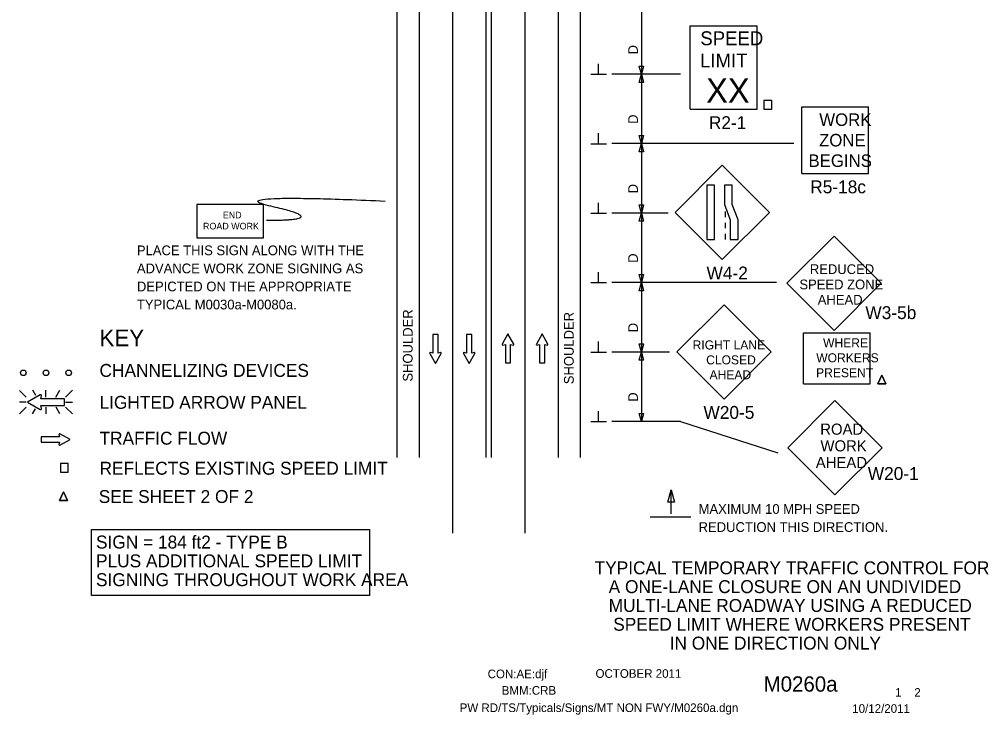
# Model space of a CAD drawing. Extents: x 16747 to 18480, y 5932 to 6921.
# Drawn here: x 16754 to 17451, y 5932 to 6432 of the extents above; entities that cross this region are included whole.
import ezdxf

# ---------------------------------------------------------------- set-up
doc = ezdxf.new("R2010")
doc.units = 0
for name, color, linetype in [('ALI_LEGAL_EX', 7, 'Continuous'), ('BORDER', 7, 'Continuous'), ('BORDER_SIGNAL_WO', 7, 'Continuous'), ('MT_SCRATCH_LEVEL_E', 7, 'Continuous'), ('PAVT_EDGE_EX', 7, 'Continuous'), ('TRAFFIC_SIGNS_PR', 7, 'Continuous'), ('TYPICAL_TEXT_DIMEN_EX', 7, 'Continuous'), ('TYPICAL_TEXT_DIMEN_PR', 7, 'Continuous')]:
    doc.layers.add(name, color=color, linetype=linetype)

msp = doc.modelspace()

# ---------------------------------------------------------------- linework, layer by layer
at = {"layer": 'ALI_LEGAL_EX'}
for p, q in [((17065.33, 6891.74), (17065.33, 6062.55)), ((17117.33, 6891.74), (17117.33, 6062.55))]:
    msp.add_line(p, q, dxfattribs=at)
for points in [[(17065.33, 6409.08), (17065.33, 6384.08)], [(17117.33, 6409.08), (17117.33, 6384.08)], [(17065.33, 6309.08), (17065.33, 6284.08)], [(17117.33, 6309.08), (17117.33, 6284.08)], [(17065.33, 6209.08), (17065.33, 6184.08)], [(17117.33, 6209.08), (17117.33, 6184.08)]]:
    msp.add_lwpolyline(points, dxfattribs=at)
at = {"layer": 'MT_SCRATCH_LEVEL_E'}
for p, q in [((17055, 6205.36), (17051.26, 6205.36)), ((17051.26, 6205.36), (17051.26, 6192.1)), ((17055, 6205.36), (17051.26, 6205.36)), ((17051.26, 6205.36), (17051.26, 6192.1)), ((17055, 6192.1), (17055, 6205.36)), ((17055, 6192.1), (17055, 6205.36)), ((17079.25, 6205.36), (17075.51, 6205.36)), ((17075.51, 6205.36), (17075.51, 6192.1)), ((17079.25, 6205.36), (17075.51, 6205.36)), ((17075.51, 6205.36), (17075.51, 6192.1)), ((17079.25, 6192.1), (17079.25, 6205.36)), ((17079.25, 6192.1), (17079.25, 6205.36)), ((17105.3, 6205.82), (17101.19, 6198.58)), ((17105.3, 6205.82), (17101.19, 6198.58)), ((17109.44, 6198.58), (17105.3, 6205.82)), ((17109.44, 6198.58), (17105.3, 6205.82)), ((17129.85, 6205.82), (17125.74, 6198.58)), ((17129.85, 6205.82), (17125.74, 6198.58)), ((17134, 6198.58), (17129.85, 6205.82)), ((17134, 6198.58), (17129.85, 6205.82)), ((17101.67, 6197.89), (17103.44, 6198.21)), ((17101.67, 6197.89), (17103.44, 6198.21)), ((17103.44, 6198.21), (17103.44, 6184.95)), ((17103.44, 6198.21), (17103.44, 6184.95)), ((17107.19, 6184.95), (17107.19, 6198.21)), ((17107.19, 6198.21), (17108.96, 6197.89)), ((17107.19, 6184.95), (17107.19, 6198.21)), ((17107.19, 6198.21), (17108.96, 6197.89)), ((17126.22, 6197.89), (17128, 6198.21)), ((17126.22, 6197.89), (17128, 6198.21)), ((17128, 6198.21), (17128, 6184.95)), ((17128, 6198.21), (17128, 6184.95)), ((17131.74, 6184.95), (17131.74, 6198.21)), ((17131.74, 6198.21), (17133.52, 6197.89)), ((17131.74, 6184.95), (17131.74, 6198.21)), ((17131.74, 6198.21), (17133.52, 6197.89)), ((17049, 6191.73), (17053.15, 6184.49)), ((17049, 6191.73), (17053.15, 6184.49)), ((17051.26, 6192.1), (17049.48, 6192.42)), ((17051.26, 6192.1), (17049.48, 6192.42)), ((17053.15, 6184.49), (17057.26, 6191.73)), ((17053.15, 6184.49), (17057.26, 6191.73)), ((17056.78, 6192.42), (17055, 6192.1)), ((17056.78, 6192.42), (17055, 6192.1)), ((17073.26, 6191.73), (17077.4, 6184.49)), ((17073.26, 6191.73), (17077.4, 6184.49)), ((17075.51, 6192.1), (17073.73, 6192.42)), ((17075.51, 6192.1), (17073.73, 6192.42)), ((17077.4, 6184.49), (17081.51, 6191.73)), ((17077.4, 6184.49), (17081.51, 6191.73)), ((17081.03, 6192.42), (17079.25, 6192.1)), ((17081.03, 6192.42), (17079.25, 6192.1)), ((17103.44, 6184.95), (17107.19, 6184.95)), ((17103.44, 6184.95), (17107.19, 6184.95)), ((17128, 6184.95), (17131.74, 6184.95)), ((17128, 6184.95), (17131.74, 6184.95)), ((16782.67, 6131.69), (16769.41, 6131.69)), ((16769.41, 6131.69), (16769.41, 6127.95)), ((16782.67, 6131.69), (16769.41, 6131.69)), ((16769.41, 6131.69), (16769.41, 6127.95)), ((16782.35, 6133.47), (16782.67, 6131.69)), ((16782.35, 6133.47), (16782.67, 6131.69)), ((16790.28, 6129.84), (16783.03, 6133.95)), ((16790.28, 6129.84), (16783.03, 6133.95)), ((16783.03, 6125.69), (16790.28, 6129.84)), ((16783.03, 6125.69), (16790.28, 6129.84)), ((16769.41, 6127.95), (16782.67, 6127.95)), ((16769.41, 6127.95), (16782.67, 6127.95)), ((16782.67, 6127.95), (16782.35, 6126.17)), ((16782.67, 6127.95), (16782.35, 6126.17))]:
    msp.add_line(p, q, dxfattribs=at)
for centre, start, end in [((17101.59, 6198.35), 150.42484, 279.96381), ((17101.59, 6198.35), 150.42484, 279.96381), ((17109.03, 6198.35), 260.03619, 29.77312), ((17109.03, 6198.35), 260.03619, 29.77312), ((17126.15, 6198.35), 150.42484, 279.96381), ((17126.15, 6198.35), 150.42484, 279.96381), ((17133.59, 6198.35), 260.03619, 29.77312), ((17133.59, 6198.35), 260.03619, 29.77312), ((17049.41, 6191.96), 80.03619, 209.77312), ((17049.41, 6191.96), 80.03619, 209.77312), ((17056.85, 6191.96), 330.42484, 99.96381), ((17056.85, 6191.96), 330.42484, 99.96381), ((17073.66, 6191.96), 80.03619, 209.77312), ((17073.66, 6191.96), 80.03619, 209.77312), ((17081.11, 6191.96), 330.42484, 99.96381), ((17081.11, 6191.96), 330.42484, 99.96381), ((16782.81, 6133.54), 60.42484, 189.96381), ((16782.81, 6133.54), 60.42484, 189.96381), ((16782.81, 6126.1), 170.03619, 299.77312), ((16782.81, 6126.1), 170.03619, 299.77312)]:
    msp.add_arc(centre, 0.463, start, end, dxfattribs=at)
at = {"layer": 'PAVT_EDGE_EX'}
for p, q in [((17025.33, 6921.02), (17025.33, 6117.01)), ((17041.33, 6921.02), (17041.33, 6117.01)), ((17089.33, 6921.02), (17089.33, 6117.01)), ((17093.33, 6921.02), (17093.33, 6117.01)), ((17141.33, 6921.02), (17141.33, 6117.01)), ((17157.33, 6921.02), (17157.33, 6117.01))]:
    msp.add_line(p, q, dxfattribs=at)
at = {"layer": 'TRAFFIC_SIGNS_PR'}
for p, q in [((17236.44, 6427.59), (17284.44, 6427.59)), ((17236.44, 6367.59), (17236.44, 6427.59)), ((17284.44, 6367.59), (17284.44, 6427.59)), ((17236.44, 6367.59), (17284.44, 6367.59)), ((17316.72, 6321.36), (17316.72, 6369.36)), ((17316.72, 6369.36), (17364.72, 6369.36)), ((17364.72, 6321.36), (17364.72, 6369.36)), ((17259.43, 6327.25), (17225.49, 6293.31)), ((17293.37, 6293.31), (17259.43, 6327.25)), ((17316.72, 6321.36), (17364.72, 6321.36)), ((17225.49, 6293.31), (17259.43, 6259.37)), ((17259.43, 6259.37), (17293.37, 6293.31)), ((17261.48, 6293.92), (17261.48, 6289.92)), ((17261.48, 6285.92), (17261.48, 6281.92)), ((17261.48, 6277.92), (17261.48, 6273.92)), ((17339.86, 6276.29), (17305.92, 6242.35)), ((17373.8, 6242.35), (17339.86, 6276.29)), ((17305.92, 6242.35), (17339.86, 6208.41)), ((17339.86, 6208.41), (17373.8, 6242.35)), ((17260.71, 6226.89), (17226.77, 6192.95)), ((17294.65, 6192.95), (17260.71, 6226.89)), ((17317.81, 6206.59), (17365.81, 6206.59)), ((17317.81, 6169.94), (17317.81, 6206.59)), ((17365.81, 6169.94), (17365.81, 6206.59)), ((17226.77, 6192.95), (17260.71, 6159.01)), ((17260.71, 6159.01), (17294.65, 6192.95)), ((16753.86, 6165.26), (16758.79, 6160.33)), ((16765.62, 6161.44), (16763.42, 6165.27)), ((16772.94, 6160.33), (16772.94, 6165.27)), ((16780.18, 6160.33), (16783.03, 6165.27)), ((16787.09, 6160.33), (16792.03, 6165.27)), ((17317.81, 6169.94), (17365.81, 6169.94)), ((16758.79, 6156.78), (16753.86, 6156.78)), ((16787.09, 6156.78), (16792.03, 6156.78)), ((17340.51, 6157.84), (17306.57, 6123.89)), ((17374.45, 6123.89), (17340.51, 6157.84)), ((16753.86, 6148.29), (16758.79, 6153.22)), ((16763.37, 6148.28), (16765.48, 6151.95)), ((16772.94, 6153.22), (16772.94, 6148.28)), ((16783.07, 6148.28), (16780.22, 6153.22)), ((16787.09, 6153.22), (16792.03, 6148.28)), ((17306.57, 6123.89), (17340.51, 6089.95)), ((17340.51, 6089.95), (17374.45, 6123.89))]:
    msp.add_line(p, q, dxfattribs=at)
for points in [[(17289.46, 6367.59), (17295.05, 6367.59), (17295.05, 6373.76), (17289.46, 6373.76)], [(17248.31, 6312.98), (17248.31, 6273.92), (17253.93, 6273.92), (17253.93, 6312.98)], [(17260.98, 6312.98), (17260.98, 6299), (17265.16, 6287.9), (17265.16, 6273.92), (17270.78, 6273.92), (17270.78, 6287.9), (17266.6, 6299), (17266.6, 6312.98)], [(16881.45, 6275.13), (16929.45, 6275.13), (16929.45, 6299.13), (16881.45, 6299.13)], [(16783.33, 6106.37), (16788.92, 6106.37), (16788.92, 6112.54), (16783.33, 6112.54)]]:
    msp.add_lwpolyline(points, close=True, dxfattribs=at)
for points in [[(17374.25, 6176.11), (17371.45, 6169.94)], [(17371.45, 6169.94), (17374.25, 6176.11)], [(17377.04, 6169.94), (17374.25, 6176.11)], [(17374.25, 6176.11), (17377.04, 6169.94)], [(17371.45, 6169.94), (17377.04, 6169.94)], [(17377.04, 6169.94), (17371.45, 6169.94)], [(16768.87, 6162.05), (16759.58, 6156.78), (16768.87, 6151.45)], [(16769.74, 6152.08), (16769.34, 6154.35), (16786.36, 6154.35), (16786.36, 6159.15), (16769.34, 6159.15), (16769.75, 6161.43)], [(16785.58, 6092.18), (16782.78, 6086.01)], [(16782.78, 6086.01), (16785.58, 6092.18)], [(16788.37, 6086.01), (16785.58, 6092.18)], [(16785.58, 6092.18), (16788.37, 6086.01)], [(16782.78, 6086.01), (16788.37, 6086.01)], [(16788.37, 6086.01), (16782.78, 6086.01)]]:
    msp.add_lwpolyline(points, dxfattribs=at)
for centre in [(16756.65, 6177.89), (16772.95, 6177.89), (16789.25, 6177.89)]:
    msp.add_circle(centre, 2, dxfattribs=at)
for centre, radius, start, end in [((16769.16, 6161.53), 0.598, 350.73078, 118.89165), ((16769.16, 6151.98), 0.597, 241.48329, 9.95933)]:
    msp.add_arc(centre, radius, start, end, dxfattribs=at)
msp.add_open_spline([(16931.67, 6287.67), (16978.9, 6287.67), (16893.88, 6307.02), (17016.98, 6301.53)], degree=2, dxfattribs=at)
at = {"layer": 'TYPICAL_TEXT_DIMEN_EX'}
msp.add_lwpolyline([(16805.73, 6065.18), (17005.7, 6065.18), (17005.7, 6017.51), (16805.73, 6017.51)], close=True, dxfattribs=at)
at = {"layer": 'TYPICAL_TEXT_DIMEN_PR'}
for p, q in [((17201.33, 6442.82), (17201.33, 6392.82)), ((17170.45, 6392.52), (17170.45, 6400.3)), ((17201.33, 6392.82), (17199.76, 6398.68)), ((17199.76, 6398.68), (17201.33, 6398.68)), ((17201.33, 6398.68), (17202.9, 6398.68)), ((17202.9, 6398.68), (17201.33, 6392.82)), ((17201.33, 6397.69), (17201.33, 6393.92)), ((17176.08, 6392.52), (17164.83, 6392.52)), ((17229.37, 6392.82), (17180.12, 6392.82)), ((17199.76, 6386.95), (17201.33, 6392.82)), ((17201.33, 6386.95), (17199.76, 6386.95)), ((17201.33, 6392.82), (17201.33, 6342.82)), ((17201.33, 6392.82), (17202.9, 6386.95)), ((17202.9, 6386.95), (17201.33, 6386.95)), ((17170.45, 6342.52), (17170.45, 6350.3)), ((17201.33, 6342.82), (17199.76, 6348.68)), ((17199.76, 6348.68), (17201.33, 6348.68)), ((17201.33, 6348.68), (17202.9, 6348.68)), ((17202.9, 6348.68), (17201.33, 6342.82)), ((17201.33, 6347.69), (17201.33, 6343.92)), ((17176.08, 6342.52), (17164.83, 6342.52)), ((17311.02, 6342.82), (17180.12, 6342.82)), ((17199.76, 6336.95), (17201.33, 6342.82)), ((17201.33, 6342.82), (17201.33, 6292.82)), ((17201.33, 6342.82), (17202.9, 6336.95)), ((17201.33, 6336.95), (17199.76, 6336.95)), ((17202.9, 6336.95), (17201.33, 6336.95)), ((17170.45, 6292.52), (17170.45, 6300.3)), ((17201.33, 6292.82), (17199.76, 6298.68)), ((17199.76, 6298.68), (17201.33, 6298.68)), ((17201.33, 6298.68), (17202.9, 6298.68)), ((17202.9, 6298.68), (17201.33, 6292.82)), ((17201.33, 6297.69), (17201.33, 6293.92)), ((17176.08, 6292.52), (17164.83, 6292.52)), ((17220.6, 6292.82), (17180.12, 6292.82)), ((17199.76, 6286.95), (17201.33, 6292.82)), ((17201.33, 6292.82), (17201.33, 6242.82)), ((17201.33, 6292.82), (17202.9, 6286.95)), ((17201.33, 6286.95), (17199.76, 6286.95)), ((17202.9, 6286.95), (17201.33, 6286.95)), ((17170.45, 6242.52), (17170.45, 6250.3)), ((17201.33, 6242.82), (17199.76, 6248.68)), ((17199.76, 6248.68), (17201.33, 6248.68)), ((17201.33, 6248.68), (17202.9, 6248.68)), ((17202.9, 6248.68), (17201.33, 6242.82)), ((17201.33, 6247.69), (17201.33, 6243.92)), ((17176.08, 6242.52), (17164.83, 6242.52)), ((17298.38, 6242.82), (17180.12, 6242.82)), ((17199.76, 6236.95), (17201.33, 6242.82)), ((17201.33, 6242.82), (17201.33, 6192.82)), ((17201.33, 6242.82), (17202.9, 6236.95)), ((17201.33, 6236.95), (17199.76, 6236.95)), ((17202.9, 6236.95), (17201.33, 6236.95)), ((17170.45, 6192.52), (17170.45, 6200.3)), ((17201.33, 6192.82), (17199.76, 6198.68)), ((17199.76, 6198.68), (17201.33, 6198.68)), ((17201.33, 6198.68), (17202.9, 6198.68)), ((17202.9, 6198.68), (17201.33, 6192.82)), ((17176.08, 6192.52), (17164.83, 6192.52)), ((17221.41, 6192.82), (17180.12, 6192.82)), ((17199.76, 6186.95), (17201.33, 6192.82)), ((17201.33, 6197.69), (17201.33, 6193.92)), ((17201.33, 6192.82), (17201.33, 6142.82)), ((17201.33, 6192.82), (17202.9, 6186.95)), ((17201.33, 6186.95), (17199.76, 6186.95)), ((17202.9, 6186.95), (17201.33, 6186.95)), ((17170.45, 6142.52), (17170.45, 6150.3)), ((17176.08, 6142.52), (17164.83, 6142.52)), ((17229.37, 6142.82), (17180.12, 6142.82)), ((17201.33, 6142.82), (17199.76, 6148.68)), ((17199.76, 6148.68), (17201.33, 6148.68)), ((17201.33, 6148.68), (17202.9, 6148.68)), ((17202.9, 6148.68), (17201.33, 6142.82)), ((17201.33, 6147.69), (17201.33, 6143.92)), ((17229.37, 6142.82), (17299.53, 6120.34)), ((17220.38, 6084.76), (17222.74, 6093.55)), ((17222.74, 6076.43), (17222.74, 6093.55)), ((17222.74, 6093.55), (17225.09, 6084.76)), ((17222.74, 6084.76), (17220.38, 6084.76)), ((17225.09, 6084.76), (17222.74, 6084.76)), ((17236.91, 6073.93), (17207.47, 6073.93))]:
    msp.add_line(p, q, dxfattribs=at)

# ---------------------------------------------------------------- texts
at = {"layer": 'BORDER'}
for s, p in [('TYPICAL TEMPORARY TRAFFIC CONTROL FOR', (17167.63, 6032.86)), ('A ONE-LANE CLOSURE ON AN UNDIVIDED', (17177.73, 6019.31)), ('MULTI-LANE ROADWAY USING A REDUCED', (17177.73, 6005.76)), ('SPEED LIMIT WHERE WORKERS PRESENT', (17181.01, 5992.21)), ('IN ONE DIRECTION ONLY', (17221.59, 5978.66))]:
    msp.add_text(s, height=9.3, dxfattribs=at).set_placement(p)
at = {"layer": 'BORDER_SIGNAL_WO'}
for s, height, p in [('CON:AE:djf', 6.2, (17090.69, 5958.06)), ('    OCTOBER 2011    ', 6.2, (17159.08, 5958.34)), ('    M0260a   ', 11, (17272.86, 5948.38)), ('BMM:CRB   ', 6.2, (17100.81, 5946.17)), (' 1    2 ', 6.2, (17381.45, 5944.7)), ('PW RD/TS/Typicals/Signs/MT NON FWY/M0260a.dgn    ', 6.2, (17070.55, 5933.71)), ('10/12/2011    ', 6.2, (17352.93, 5933.13))]:
    msp.add_text(s, height=height, dxfattribs=at).set_placement(p)
at = {"layer": 'TRAFFIC_SIGNS_PR'}
for s, height, p in [('SPEED', 10, (17243.65, 6413.67)), ('LIMIT', 10, (17243.45, 6397.67)), ('XX', 17.538, (17247.83, 6372.29)), ('R2-1', 9.3, (17249.79, 6353.29)), ('WORK', 9.021, (17329.22, 6355.57)), ('ZONE', 9.021, (17329.07, 6340.81)), ('BEGINS', 9.021, (17321.48, 6326.05)), ('R5-18c', 9.3, (17322.73, 6307.06)), ('END', 4.789, (16900.2, 6289.04)), ('ROAD WORK', 4.789, (16885.96, 6281.06)), ('PLACE THIS SIGN ALONG WITH THE', 7, (16838.39, 6262.52)), ('ADVANCE WORK ZONE SIGNING AS', 7, (16838.39, 6249.52)), ('W4-2', 9.3, (17248.13, 6245.06)), ('REDUCED', 7, (17322.43, 6248.98)), ('DEPICTED ON THE APPROPRIATE', 7, (16838.39, 6236.52)), ('SPEED ZONE', 7, (17314.92, 6237.98)), ('AHEAD', 7, (17328.12, 6226.98)), ('TYPICAL M0030a-M0080a.', 7, (16838.39, 6223.52)), ('W3-5b', 9.3, (17362.39, 6216.54)), ('RIGHT LANE', 6.5, (17238.11, 6194.69)), ('WHERE', 6.5, (17331.95, 6196.19)), ('WORKERS', 6.5, (17327.04, 6185.44)), ('CLOSED', 6.5, (17247.85, 6183.94)), ('AHEAD', 6.5, (17250.28, 6173.19)), ('PRESENT', 6.5, (17326.95, 6174.69)), ('W20-5', 9.3, (17245.93, 6144.71)), ('ROAD', 8, (17329.93, 6133.31)), ('WORK', 8, (17330.07, 6121.31)), ('AHEAD', 8, (17326.71, 6109.31)), ('W20-1', 9.3, (17364.12, 6100.74))]:
    msp.add_text(s, height=height, dxfattribs=at).set_placement(p)
at = {"layer": 'TYPICAL_TEXT_DIMEN_EX'}
for s, height, p in [('KEY', 12, (16811.49, 6197)), ('CHANNELIZING DEVICES', 9.3, (16811.49, 6174.95)), ('LIGHTED ARROW PANEL', 9.3, (16811.49, 6151.95)), ('TRAFFIC FLOW', 9.3, (16811.49, 6126.15)), ('REFLECTS EXISTING SPEED LIMIT', 9.3, (16811.49, 6104.53)), ('SEE SHEET 2 OF 2', 9.3, (16810.95, 6084.17)), ('SIGN = 184 ft2 - TYPE B', 9.3, (16808.97, 6051.41)), ('PLUS ADDITIONAL SPEED LIMIT', 9.3, (16808.97, 6037.86)), ('SIGNING THROUGHOUT WORK AREA', 9.3, (16808.97, 6024.31))]:
    msp.add_text(s, height=height, dxfattribs=at).set_placement(p)
at = {"layer": 'TYPICAL_TEXT_DIMEN_PR'}
for s, p in [('D', (17198.77, 6407.04)), ('D', (17198.77, 6357.04)), ('D', (17198.77, 6307.04)), ('D', (17198.77, 6257.04)), ('SHOULDER', (17036.71, 6171.54)), ('SHOULDER', (17152.61, 6169.66)), ('D', (17198.77, 6207.04)), ('D', (17198.77, 6157.04))]:
    msp.add_text(s, height=7, rotation=90, dxfattribs=at).set_placement(p)
for s, p in [('MAXIMUM 10 MPH SPEED', (17242.43, 6076.35)), ('REDUCTION THIS DIRECTION.', (17242.43, 6063.35))]:
    msp.add_text(s, height=7, dxfattribs=at).set_placement(p)

doc.saveas('drawing.dxf')
